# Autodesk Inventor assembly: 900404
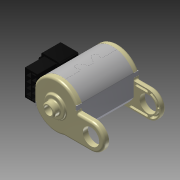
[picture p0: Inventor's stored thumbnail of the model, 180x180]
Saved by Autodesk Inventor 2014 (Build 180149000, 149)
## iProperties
Created: 2007-10
Part Number: 900404
Document SubType Name: Assembly
Designer: TH
Mass: 84.5508 g
Surface Area: 361.459 cm^2
Volume: 32.7287 cm^3
Density: 2.58338 g/cm^3
Description: SERVO MOTOR 1000
Component Category: Electrical
Author: TH
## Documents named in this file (5)
- C:\Users\iTools\Desktop\tutorial files\Automotive\9000\900404.iam
- C:\Users\iTools\Desktop\tutorial files\Automotive\9000\900985.ipt
- C:\Users\iTools\Desktop\tutorial files\Automotive\9000\901230.ipt
- C:\Users\iTools\Desktop\tutorial files\Automotive\9000\900684.ipt
- C:\Users\iTools\Desktop\tutorial files\Automotive\9000\900025.ipt
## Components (4 placed, 4 different names)
1. 900985:1
2. 901230:1
3. 900684:1
4. 900025:1
